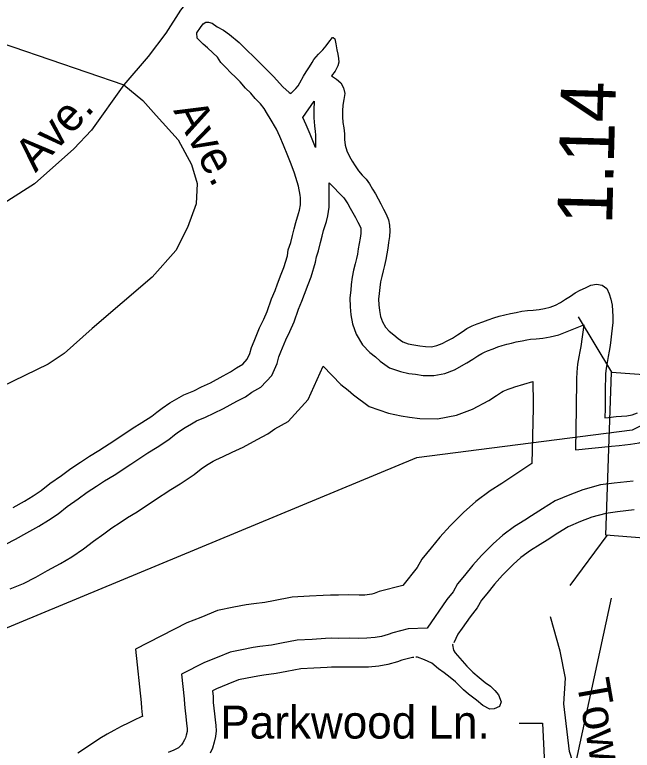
# Model space of a CAD drawing. Extents: x 2104537 to 2336408, y 34176 to 229611.
# Drawn here: x 2135347 to 2136753, y 50450 to 52123 of the extents above; entities that cross this region are included whole.
import ezdxf

# ---------------------------------------------------------------- set-up
doc = ezdxf.new("R2010")
doc.units = 0
for name, color, linetype in [('Exist Boundary Political City Limit New', 7, 'Continuous'), ('Exist Hydrographic Buffer Line', 7, 'Continuous'), ('Exist Hydrographic River Shore', 7, 'Continuous'), ('Exist Road Non-System Type 51', 7, 'Continuous'), ('Exist Road Non-System Type 51 Label', 7, 'Continuous'), ('Exist Road Primary NC Mileage Hundredths English Label', 7, 'Continuous'), ('Exist Road Primary NC Structure Standard Bridge CELL', 7, 'Continuous'), ('Exist Road Primary NC Structure Standard Bridge Number Label', 7, 'Continuous'), ('Map Preparation Boundary City Limit Buffer Line', 7, 'Continuous')]:
    doc.layers.add(name, color=color, linetype=linetype)

msp = doc.modelspace()

# ---------------------------------------------------------------- linework, layer by layer
at = {"layer": 'Exist Boundary Political City Limit New'}
msp.add_lwpolyline([(2137310.8, 51451.8), (2136753.2, 51178.3), (2136262.2, 51114.9), (2135088.2, 50627.9), (2135057, 50833.1), (2134780.2, 50660.2), (2134143.5, 50557.9), (2133816, 50577.1), (2133616.5, 50503.9)], dxfattribs=at)
at = {"layer": 'Exist Hydrographic Buffer Line'}
for points in [[(2136003.1, 51889.2), (2136029.2, 51926.9)], [(2136029.2, 51926.9), (2136027.8, 51906.4), (2136027.9, 51888.4), (2136029.3, 51870.1), (2136031.4, 51857.6), (2136032, 51849.6), (2136032.2, 51821.4)], [(2136032.2, 51821.4), (2136019.6, 51851.6), (2136010.9, 51873), (2136003.1, 51889.2)], [(2135326.7, 50918.7), (2135348.6, 50930.4), (2135374.8, 50944.8), (2135402.2, 50959.7), (2135424.4, 50973.2), (2135445.9, 50987.4), (2135466.9, 51004.2), (2135491.8, 51022), (2135512.2, 51037), (2135533.2, 51050.5), (2135551.9, 51063.1), (2135573.7, 51075.7), (2135611.3, 51100.7), (2135650, 51126.5), (2135671.6, 51139.6), (2135697.8, 51156.5), (2135711.2, 51167.5), (2135720.3, 51174.4), (2135735.5, 51184.3), (2135749.4, 51192.6), (2135761.3, 51199.3), (2135781.6, 51207.9), (2135800.5, 51216.9), (2135822.4, 51227.2), (2135852.6, 51243.7), (2135872.3, 51254.1), (2135887.3, 51264.3), (2135907.7, 51276), (2135932.3, 51302.6), (2135944.4, 51329.8), (2135948.7, 51344.8), (2135953.2, 51356.3), (2135964.2, 51383.8), (2135973.6, 51402.3), (2135983.3, 51424.3), (2135993.2, 51453.2), (2136001.1, 51471.8), (2136007.1, 51487.7), (2136015.3, 51509.7), (2136021.9, 51526.8), (2136032.2, 51560.2), (2136033.9, 51572.7), (2136038.7, 51585.8), (2136043.3, 51605.3), (2136047, 51619.6), (2136050.5, 51632.4), (2136056.6, 51653.1), (2136059.8, 51665.3), (2136063, 51685), (2136063, 51740.5)], [(2136063, 51740.5), (2136096.6, 51706.8), (2136099.7, 51702.4), (2136105.6, 51692.7), (2136111.2, 51683.3), (2136122.9, 51661.8), (2136128.6, 51650.9), (2136133.5, 51641.5), (2136135.1, 51637.5), (2136135.2, 51637.3), (2136135.3, 51632.8), (2136134.8, 51625.4), (2136133.3, 51614.7), (2136131.5, 51602.4), (2136129.4, 51590.2), (2136127.4, 51578.6), (2136125.1, 51568.3), (2136122.2, 51556.6), (2136118.6, 51542.1), (2136115.2, 51526.1), (2136113.2, 51509.3), (2136112, 51496.2), (2136109.9, 51479.1), (2136110.6, 51458.6), (2136112.5, 51440.6), (2136116.2, 51420.1), (2136124.4, 51396.2), (2136138.8, 51372.4), (2136155.7, 51354.8), (2136168.7, 51344.5), (2136179.4, 51335.3), (2136200.2, 51320.1), (2136225.1, 51311.5), (2136244.3, 51307.3), (2136259.8, 51305.1), (2136277.3, 51302.6), (2136301.2, 51302.1), (2136326.2, 51306.9), (2136348, 51315.2), (2136376.7, 51330.9), (2136390.4, 51339.4), (2136401.8, 51347), (2136410.3, 51352.5), (2136416.3, 51355.7), (2136423.8, 51358.7), (2136436.1, 51363.3), (2136446.9, 51367.4), (2136457, 51370.7), (2136467.2, 51373.7), (2136478, 51376.3), (2136489, 51378.9), (2136502.1, 51381.3), (2136512.8, 51383.8), (2136521.4, 51384.7), (2136534.5, 51386.1), (2136549.4, 51387.6), (2136566.3, 51390.3), (2136586.1, 51395), (2136643, 51417.5)], [(2136623.8, 51133), (2136705.7, 51141.6), (2136723.4, 51143.5), (2136749, 51145.8), (2136768.5, 51149.2), (2136786.8, 51155.2), (2136801.6, 51160.8), (2136821.8, 51171.2), (2136845, 51194.2), (2136852.6, 51204.9), (2136860.1, 51213.9), (2136869.5, 51226.4), (2136884.3, 51251.9), (2136891.6, 51266.5), (2136897.8, 51286.1), (2136898.3, 51310.2), (2136893.8, 51334.9), (2136881.6, 51358.1), (2136872.4, 51367.6), (2136875.4, 51388.5), (2136877.3, 51403.5), (2136888, 51467.1)], [(2136643, 51417.5), (2136635.9, 51368.2), (2136634, 51357.3), (2136631.5, 51344.8), (2136628.2, 51327.8), (2136627, 51309.8), (2136626.3, 51295), (2136626, 51281.1), (2136625.8, 51268), (2136625.5, 51254), (2136625.6, 51240.1), (2136625.7, 51227.8), (2136623.8, 51133)], [(2135336.6, 50817.2), (2135367.4, 50828.9), (2135395.5, 50843.8), (2135422.1, 50858.5), (2135451.3, 50874.4), (2135477, 50890), (2135503.9, 50907.7), (2135526.3, 50925.7), (2135549.7, 50942.3), (2135568.2, 50956), (2135587.3, 50968.3), (2135604.1, 50979.6), (2135625.7, 50992.1), (2135665.7, 51018.8), (2135702.9, 51043.4), (2135723.8, 51056.2), (2135755.9, 51076.8), (2135772, 51090.1), (2135776.9, 51093.7), (2135787.8, 51100.9), (2135798.6, 51107.4), (2135804.7, 51110.8), (2135822, 51118.1), (2135842.5, 51127.9), (2135867, 51139.4), (2135899.1, 51157), (2135923.2, 51169.6), (2135939.5, 51180.8), (2135969.7, 51198), (2136015.5, 51247.7), (2136049.4, 51323.3)], [(2136049.4, 51323.3), (2136089.5, 51281.7), (2136106, 51268.7), (2136118.1, 51258.1), (2136154.3, 51231.9), (2136198.4, 51216.6), (2136226.6, 51210.4), (2136245.9, 51207.6), (2136269.4, 51204.3), (2136309.6, 51203.5), (2136353.2, 51211.8), (2136389.4, 51225.7), (2136426.2, 51245.8), (2136443.7, 51256.7), (2136455.6, 51264.6), (2136459, 51266.8), (2136459.1, 51266.8), (2136470.9, 51271.2), (2136479.6, 51274.5), (2136485.9, 51276.6), (2136526.9, 51288.7)], [(2136526.9, 51288.7), (2136527.2, 51239.5), (2136527.2, 51228.4), (2136524.8, 51102)], [(2136524.8, 51102), (2136469.9, 51065.4), (2136455.9, 51056.5), (2136429.8, 51040.2), (2136396.6, 51016), (2136368.5, 50991), (2136338.6, 50960.6), (2136315.2, 50934.7), (2136295.2, 50910.1), (2136273.8, 50884.4), (2136263.3, 50865.4), (2136230.4, 50824.6)], [(2136755, 51062.1), (2136711.7, 51057.3), (2136680.5, 51053.3), (2136640.8, 51042.6), (2136610.8, 51031), (2136577.5, 51016.9), (2136548.4, 50999.4), (2136523.6, 50983), (2136508.5, 50973.3), (2136484.9, 50958.6), (2136458.4, 50939.3), (2136436.4, 50919.6), (2136410.2, 50893), (2136389.9, 50870.7), (2136371.3, 50847.6), (2136355.4, 50828.6), (2136345.3, 50810.3), (2136331.2, 50792.8), (2136286.3, 50727.8)], [(2136230.4, 50824.6), (2136176.8, 50811), (2136165.2, 50806.2), (2136160.1, 50804.8), (2136154.6, 50803.8), (2136144.1, 50802.9), (2136131, 50802.7), (2136108.1, 50803.2), (2136084.2, 50802.7), (2136066, 50803), (2136049, 50802.2), (2136018.3, 50800.1), (2135978.6, 50797.9), (2135936.4, 50790), (2135916.5, 50786.3), (2135891.6, 50783), (2135873.7, 50780.4), (2135846, 50775.2), (2135808.5, 50768), (2135770.6, 50752), (2135738.8, 50739.5), (2135622.3, 50679.9)], [(2136286.3, 50727.8), (2136243.1, 50726.3), (2136207.8, 50717.3), (2136197.2, 50712.9), (2136181.9, 50708.7), (2136167.6, 50706.2), (2136149, 50704.5), (2136130.6, 50704.3), (2136108.2, 50704.7), (2136084.3, 50704.2), (2136067.4, 50704.6), (2136054.6, 50703.9), (2136024.4, 50701.9), (2135990.4, 50699.9), (2135954.4, 50693.2), (2135932, 50689.1), (2135905.3, 50685.5), (2135889.8, 50683.3), (2135864.3, 50678.5), (2135837.3, 50673.3), (2135807.8, 50660.9), (2135779.4, 50649.7), (2135727.2, 50623)], [(2135622.3, 50679.9), (2135635, 50558.8), (2135635.8, 50545.6), (2135637.4, 50530.5), (2135637.7, 50526.6), (2135634.9, 50525.5), (2135618.8, 50517.9), (2135606.9, 50512.5), (2135589.2, 50504.1), (2135572.7, 50495.1), (2135557.5, 50486.5), (2135540.8, 50476.2), (2135528.9, 50468.2), (2135518, 50461.2), (2135506, 50453.3), (2135490.6, 50443.1)], [(2135727.2, 50623), (2135733.2, 50566.7), (2135733.9, 50553.5), (2135735.4, 50539.6), (2135736.4, 50526.4), (2135738.1, 50510.9), (2135739.9, 50499.1), (2135740, 50496.7), (2135739.5, 50492.7), (2135737.6, 50484.2), (2135735.7, 50477.7), (2135733.6, 50473.2), (2135730, 50466.9), (2135726.6, 50461.9), (2135722.6, 50457.6), (2135719.9, 50455.1), (2135718.6, 50454.4), (2135709.1, 50450.2), (2135696.6, 50444.4)]]:
    msp.add_lwpolyline(points, dxfattribs=at)
at = {"layer": 'Exist Hydrographic River Shore'}
for points in [[(2135984, 51762.4), (2135981.2, 51771), (2135975.3, 51786.8), (2135969, 51802.4), (2135959, 51826.5), (2135950.9, 51846.4), (2135943, 51862.9), (2135929, 51886.8), (2135922.6, 51896.8), (2135914.7, 51910.1), (2135906.7, 51920.1), (2135894.8, 51932.8), (2135884.8, 51944.4), (2135872.6, 51956.2), (2135860.7, 51970.2), (2135850.4, 51980.2), (2135838.5, 51991.9), (2135828.5, 52002), (2135816.6, 52014.7), (2135808.6, 52026.3), (2135798.3, 52036.4), (2135786.4, 52048.1), (2135776.4, 52056.5), (2135770.3, 52062.2), (2135762.6, 52069.9), (2135762.1, 52082), (2135770.3, 52094.3), (2135776.3, 52102.4), (2135782.3, 52106.2), (2135788.2, 52106.1), (2135796.4, 52104.3), (2135808.3, 52095.9)], [(2135808.3, 52095.9), (2135822.3, 52088.4), (2135836.2, 52078.3), (2135858.2, 52059.8), (2135876.2, 52042.1), (2135891, 52028), (2135914.2, 52004.6), (2135936.4, 51982.8), (2135957.6, 51959.4), (2135971.8, 51946.1), (2135975.4, 51944.3), (2135980.4, 51948.2), (2135987.4, 51955.6), (2135992.8, 51961.1), (2135996.5, 51968.5), (2136004.7, 51983.2), (2136010.4, 51992.9), (2136018.6, 52004.9), (2136024.3, 52014.6), (2136028.4, 52021.1), (2136038.5, 52033.4), (2136048.5, 52043), (2136056.2, 52052.7), (2136062.3, 52060.8), (2136070.4, 52071.1), (2136072.3, 52071.1), (2136076.2, 52068.7), (2136078.3, 52057.2), (2136080.3, 52043), (2136082.4, 52033.2), (2136084.5, 52023.3), (2136084.7, 52015.1), (2136082.6, 52006.9), (2136076.4, 51994.9), (2136068.7, 51984.2)], [(2136068.7, 51984.2), (2136079.4, 51976.8), (2136089.4, 51968.4), (2136095.4, 51956.8), (2136098.4, 51943.6), (2136096.2, 51930.5), (2136094.3, 51917.4), (2136093.4, 51904.3), (2136093.5, 51891.2), (2136094.5, 51878.1), (2136096.6, 51865.5), (2136097.6, 51852.4), (2136097.7, 51839.3), (2136099.1, 51826.1), (2136103.1, 51813.9), (2136109, 51801)], [(2136109, 51801), (2136115.1, 51789.7), (2136122.1, 51779.1), (2136129.5, 51768.1), (2136138.1, 51758.1), (2136147.2, 51749.1), (2136154.8, 51738.1), (2136161.8, 51726.5), (2136168.2, 51715.9), (2136174.5, 51704.2), (2136180.9, 51692.6), (2136186.9, 51681), (2136192.9, 51669.4), (2136198.2, 51656.9), (2136200.6, 51644.7), (2136201, 51631.5), (2136200.1, 51618.4), (2136198.2, 51605.3), (2136196.3, 51592.3), (2136194.1, 51579.2), (2136191.9, 51566.1), (2136189, 51553), (2136185.8, 51540.6), (2136182.6, 51527.6), (2136180.1, 51515.5), (2136178.5, 51502.4), (2136177.2, 51489.3), (2136175.7, 51476.2), (2136176.1, 51463), (2136177.5, 51449.9), (2136179.8, 51436.7), (2136184.2, 51424.2), (2136191.2, 51412.5), (2136199.9, 51403.5), (2136210.5, 51395.1), (2136220.2, 51386.7), (2136230.9, 51379), (2136243, 51374.8), (2136256, 51371.9), (2136269.1, 51370), (2136282.5, 51368.1), (2136295.7, 51367.9), (2136308.2, 51370.3), (2136320.4, 51374.9), (2136332, 51381.3), (2136343.6, 51387.6), (2136354.9, 51394.6), (2136365.9, 51402), (2136376.8, 51409), (2136388.4, 51415.3), (2136400.3, 51420), (2136412.9, 51424.7), (2136425.1, 51429.4), (2136437.7, 51433.4), (2136450.2, 51437.1), (2136462.8, 51440.1), (2136475.6, 51443.1), (2136488.8, 51445.5), (2136501.6, 51448.5), (2136514.5, 51449.9), (2136527.6, 51451.3), (2136540.8, 51452.7), (2136553.6, 51454.8), (2136566.5, 51457.8), (2136578.4, 51462.5), (2136589.6, 51468.8), (2136600.9, 51476.2), (2136612.2, 51483.2), (2136623.2, 51490.5), (2136634.8, 51496.8), (2136646.7, 51502.2), (2136659, 51507.9), (2136671.5, 51509.9), (2136684.9, 51508), (2136694.9, 51500.6), (2136700.6, 51488), (2136704.3, 51475.8), (2136707, 51462.6), (2136708.4, 51449.5), (2136708.8, 51436.3), (2136708.5, 51423.2), (2136707.3, 51410.1)], [(2135343.3, 51002.4), (2135369.5, 51016.6), (2135389.4, 51028.7), (2135407.3, 51040.5), (2135427.3, 51056.5), (2135453.3, 51075.1), (2135474.9, 51091), (2135497.2, 51105.4), (2135517.1, 51118.8), (2135539, 51131.5), (2135574.9, 51155.4), (2135614.8, 51181.9), (2135636.7, 51195.2), (2135659, 51209.5), (2135670.7, 51219.2), (2135682.6, 51228.1), (2135700.6, 51239.9), (2135716.5, 51249.5), (2135732.4, 51258.3), (2135754.6, 51267.7), (2135772.5, 51276.3), (2135792.7, 51285.7), (2135821.5, 51301.6), (2135838.5, 51310.4), (2135852.4, 51320), (2135866.4, 51327.9), (2135876.7, 51339.2), (2135882.6, 51352.2), (2135886.4, 51365.9), (2135892.3, 51380.6), (2135904.4, 51410.9), (2135914.3, 51430.4), (2135922.2, 51448.3), (2135931.9, 51476.6), (2135940.1, 51496.1), (2135945.7, 51510.8), (2135954, 51533), (2135959.9, 51548.3), (2135967.9, 51574.4), (2135969.8, 51588.4), (2135975.7, 51604.7), (2135979.6, 51621.1), (2135983.5, 51636.4), (2135987.4, 51650.4), (2135993.4, 51670.7), (2135995.5, 51678.8), (2135997.4, 51690.3), (2135997.4, 51706.7), (2135997.2, 51712.6), (2135993.3, 51733), (2135987.1, 51752.8), (2135984, 51762.4)], [(2136707.3, 51410.1), (2136706, 51397), (2136704.5, 51383.9), (2136702.6, 51370.8), (2136700.7, 51357.8), (2136698.5, 51345.3), (2136695.9, 51332.2), (2136693.4, 51319.2), (2136692.5, 51306.1), (2136691.9, 51293), (2136691.6, 51279.8), (2136691.4, 51266.7), (2136691.1, 51253.6), (2136691.2, 51240.5), (2136691.3, 51227.3), (2136690.9, 51206)], [(2136690.9, 51206), (2136698.8, 51206.8), (2136716.8, 51208.8), (2136740.5, 51211), (2136752.7, 51213), (2136764.9, 51217.1)], [(2136757.4, 50996.4), (2136719.6, 50992.2), (2136693.2, 50988.8), (2136661.2, 50980.2), (2136635.5, 50970.2), (2136607.3, 50958.3), (2136583.4, 50944), (2136559.5, 50928), (2136543.6, 50917.8), (2136521.6, 50904.1), (2136499.7, 50888.1), (2136481.6, 50872.1), (2136457.9, 50847.9), (2136439.8, 50827.9), (2136422, 50806), (2136409.9, 50791.4), (2136400, 50773.6), (2136383.9, 50753.6), (2136366, 50727.7), (2136356.2, 50713.7), (2136346.7, 50694.4)], [(2136345.3, 50691.5), (2136344.2, 50689.4), (2136346.3, 50677.8), (2136350.1, 50671.2), (2136360.4, 50659.5), (2136376.4, 50641.2), (2136390.3, 50627.8), (2136404.5, 50615.3), (2136418.4, 50603.6), (2136430.7, 50595.8), (2136440.3, 50585.8), (2136448.7, 50575.8), (2136454.6, 50560.2), (2136450.5, 50549.5), (2136438.6, 50544.1), (2136428.7, 50543.3), (2136412.8, 50551.9), (2136398.6, 50563.6), (2136380.5, 50577.1), (2136368.5, 50587.2), (2136350.5, 50605.6), (2136338.5, 50615.6), (2136324.6, 50625.7), (2136312.3, 50635.2), (2136296.5, 50647.6), (2136280.3, 50655.5), (2136264.3, 50661.4), (2136260.6, 50661.2)], [(2136256, 50661.1), (2136252.5, 50660.9), (2136228.4, 50654.8), (2136218.5, 50650.8), (2136196.4, 50644.6), (2136176.3, 50641.1), (2136152.3, 50638.9), (2136130.3, 50638.7), (2136108.3, 50639.1), (2136084.4, 50638.6), (2136068.3, 50638.9), (2136058.4, 50638.4), (2136028.5, 50636.4), (2135998.3, 50634.7), (2135966.4, 50628.7), (2135942.3, 50624.3), (2135914.4, 50620.5), (2135900.6, 50618.5), (2135876.5, 50614.1), (2135856.4, 50610.2), (2135832.6, 50600.1), (2135806.5, 50589.8), (2135797.2, 50585.1)], [(2135797.2, 50585.1), (2135798.6, 50571.9), (2135799.3, 50558.8), (2135800.7, 50545.6), (2135801.8, 50532.5), (2135803.2, 50519.3), (2135805.2, 50506.2), (2135805.9, 50494), (2135804.1, 50480.9), (2135801.2, 50467.9), (2135797.3, 50454.8), (2135792.2, 50443.4)]]:
    msp.add_lwpolyline(points, dxfattribs=at)
at = {"layer": 'Exist Road Non-System Type 51'}
for points in [[(2135803.7, 52503.1), (2135821.6, 52407.9), (2135839.6, 52332.5), (2135839.6, 52298.4), (2135827, 52269.7), (2135796, 52223.8), (2135724.4, 52133.6), (2135690.9, 52081.4), (2135651.1, 52028.5), (2135595.5, 51963.9)], [(2134677.2, 52374.4), (2134721.4, 52348.1), (2134768, 52306.8), (2134888.3, 52181.1), (2134925.9, 52152.4), (2134983.4, 52130.8), (2135175.6, 52094.9), (2135258.1, 52078.8), (2135595.5, 51963.9)], [(2135595.5, 51963.9), (2135521.6, 51860.6), (2135482.1, 51818.4), (2135392.3, 51738.1), (2135331.7, 51700), (2135274.3, 51665.9), (2135179.2, 51617.4), (2135119.9, 51583.3), (2135078.7, 51561.7)], [(2135595.5, 51963.9), (2135638.5, 51928), (2135669.1, 51893.9), (2135719.3, 51838.2), (2135749.8, 51782.5), (2135762.4, 51739.5), (2135760.6, 51692.8), (2135740.8, 51638.9), (2135713.9, 51586.9), (2135660.1, 51525.8), (2135523.7, 51409.1), (2135459.9, 51352.2), (2135423.2, 51328.3), (2135317.3, 51276.3), (2135265.3, 51260.1), (2135231.2, 51254.7)], [(2136634.5, 50343.5), (2136618, 50423.5), (2136609.9, 50447.3), (2136597.6, 50555.5), (2136601.3, 50613.5), (2136589.1, 50675.4), (2136566.6, 50753.3)]]:
    msp.add_lwpolyline(points, dxfattribs=at)
at = {"layer": 'Exist Road Non-System Type 51 Label'}
msp.add_lwpolyline([(2136495.8, 50511.6), (2136548.7, 50511.6), (2136558.4, 50309.3)], dxfattribs=at)
at = {"layer": 'Exist Road Primary NC Structure Standard Bridge CELL'}
for p, q in [((2136629.6, 51436.1), (2136705.5, 51310.1)), ((2136695, 50938.6), (2136611.1, 50824.8))]:
    msp.add_line(p, q, dxfattribs=at)
msp.add_lwpolyline([(2136821.1, 51301.3), (2136808.6, 50930), (2136693, 50938.8), (2136705.5, 51310.1)], close=True, dxfattribs=at)
at = {"layer": 'Exist Road Primary NC Structure Standard Bridge Number Label'}
msp.add_line((2136704.9, 50796), (2136500.2, 49847.1), dxfattribs=at)
at = {"layer": 'Map Preparation Boundary City Limit Buffer Line'}
msp.add_lwpolyline([(2137310.8, 51451.8), (2136753.2, 51178.3), (2136262.2, 51114.9), (2135088.2, 50627.9), (2135057, 50833.1), (2134780.2, 50660.2), (2134143.5, 50557.9), (2133816, 50577.1), (2133616.5, 50503.9)], dxfattribs=at)

# ---------------------------------------------------------------- texts
at = {"layer": 'Exist Road Non-System Type 51 Label'}
for s, rotation, p in [('Ave.', 46.8802, (2135394.5, 51762.5)), ('Ave.', 297.6879, (2135707.5, 51905.1)), ('Townview', 279.9652, (2136626, 50606.2))]:
    msp.add_text(s, height=75, rotation=rotation, dxfattribs=at).set_placement(p)
msp.add_text('Parkwood Ln.', height=75, dxfattribs=at).set_placement((2135815.3, 50476.4))
at = {"layer": 'Exist Road Primary NC Mileage Hundredths English Label'}
msp.add_text('1.14', height=125, rotation=88.4032, dxfattribs=at).set_placement((2136707.1, 51644.9))

doc.saveas('drawing.dxf')
